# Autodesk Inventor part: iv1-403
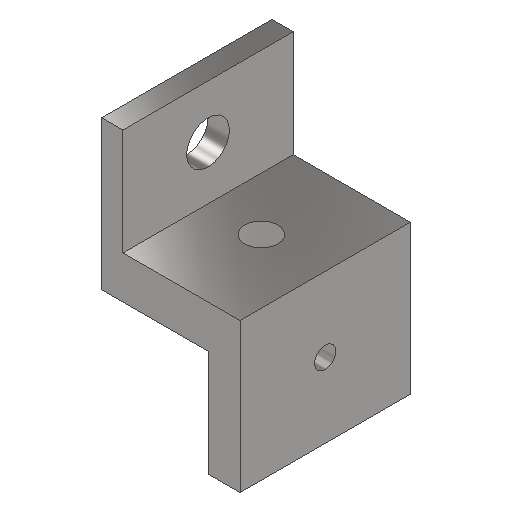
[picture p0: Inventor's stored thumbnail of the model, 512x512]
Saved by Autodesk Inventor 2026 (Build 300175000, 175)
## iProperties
Shininess: 64.0
Angle Display Precision: 2
Document Length Units: 11269
Document Angle Units: 11279
Document Time Units: 11290
Document Mass Units: 11283
Document Length Units Precision: 3
Document Angle Units Precision: 2
Created: 2002-04
Part Number: iv1-403
Document SubType Name: Modeling
Designer: Lars Bertram Pedersen
Material: Steel, Mild
Density: 7.85 g/cm^3
Appearance: Semi-Polished
Mass: 1537.87 g
Surface Area: 356.107 cm^2
Volume: 195.906 cm^3
Density: 0.0
Volumn: 0.0
Area: 0.0
PropertySet Name: Model Information
Control State: 0
Master: False
Checked Out: False
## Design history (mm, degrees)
sketch "Sketch1"
  geometry: L1 (-50, 120)-(-40, 120); L2 (-40, 120)-(-40, 70); L3 (-40, 70)-(15, 70); L4 (15, 70)-(15, 0); L5 (15, 0)-(0, 0); L6 (0, 0)-(0, 50); L7 (0, 50)-(-50, 50); L8 (-50, 50)-(-50, 120); 1 further point
  constraints: 16 end point, 4 parallel, 3 perpendicular, 1 coincident, 1 horizontal
  dimensions: "d3" = 50 distance of L6.end L7.end; "d4" = 15 distance of L4.end L5.end; "d5" = 50 distance between parallel lines of L5 L7; "d8" = 50 distance of L1.end L2.end; "d9" = 10 distance of L1.start L1.end; "d10" = 20 distance between parallel lines of L7 L3
extrude "Extrusion1" new body sketch "Sketch1" distance "d11" = 80; taper "d12" = 0 deg
sketch "Sketch2"
  geometry: L1 (0, 50)-(0, 0) reference; L2 (0, 50)-(-80, 50) reference; C1 r 10 at (-40, 25)
  constraints: 1 centre point
  dimensions: "d13" = 20 diameter of C1; "d14" = 25 distance from line of L2 C1.centre; "d15" = 40 distance from line of L1 C1.centre
extrude "Extrusion2" cut sketch "Sketch2" extent not by distance; stored distance "d16" = 50; taper "d17" = 0 deg
sketch "Sketch4"
  geometry: L1 (-80, 70)-(-80, 0) reference; L2 (0, 0)-(-80, 0) reference; C1 r 5 at (-40, 35)
  constraints: 1 centre point
  dimensions: "d23" = 10 diameter of C1; "d24" = 40 distance from line of L1 C1.centre; "d25" = 35 distance from line of L2 C1.centre
extrude "Extrusion4" cut sketch "Sketch4" stored distance "d26" = 50; taper "d27" = 0 deg
sketch "Sketch5"
  geometry: L1 (0, 0)-(0, -80) reference; L2 (0, -80)-(55, -80) reference; C1 r 7.75 at (25, -40); 1 further point
  constraints: 1 centre point
  dimensions: "d28" = 25 distance from line of C1.centre L1; "d29" = 40 distance from line of L2 C1.centre; "d30" = 15.5 diameter of C1
extrude "Extrusion5" cut sketch "Sketch5" extent not by distance; stored distance "d31" = 0; taper "d32" = 0 deg
body "Solid1"
